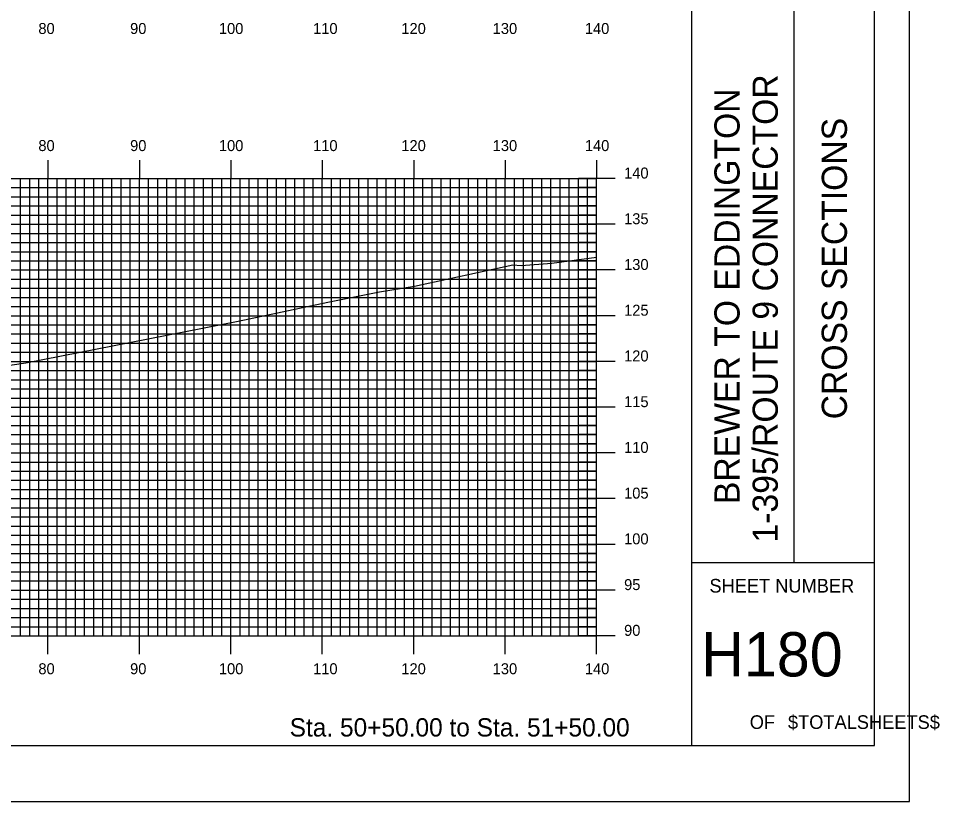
# Model space of a CAD drawing. Extents: x 1755495 to 1755838, y 442591 to 442811.
# Drawn here: x 1755737.3 to 1755838, y 442590.5 to 442676.2 of the extents above; entities that cross this region are included whole.
import ezdxf

# ---------------------------------------------------------------- set-up
doc = ezdxf.new("R2010")
doc.units = 0
for name, color, linetype in [('BORDER', 7, 'Continuous'), ('H_V ANNOTATION', 7, 'Continuous'), ('MAJOR', 7, 'Continuous'), ('MINOR', 7, 'Continuous'), ('PLOT BOUNDARY', 7, 'Continuous'), ('S_Roadway_Centerline', 7, 'Continuous')]:
    doc.layers.add(name, color=color, linetype=linetype)

msp = doc.modelspace()

# ---------------------------------------------------------------- linework, layer by layer
at = {"layer": 'BORDER'}
for p, q in [((1755810.94, 442596.67), (1755810.94, 442806.67)), ((1755822.13, 442616.67), (1755822.13, 442686.67)), ((1755810.94, 442616.67), (1755830.94, 442616.67))]:
    msp.add_line(p, q, dxfattribs=at)
msp.add_lwpolyline([(1755510.94, 442596.67), (1755830.94, 442596.67), (1755830.94, 442806.67), (1755510.94, 442806.67)], close=True, dxfattribs=at)
at = {"layer": 'MAJOR'}
for p, q in [((1755740.54, 442660.67), (1755740.54, 442658.67)), ((1755750.54, 442660.67), (1755750.54, 442658.67)), ((1755760.54, 442660.67), (1755760.54, 442658.67)), ((1755770.54, 442660.67), (1755770.54, 442658.67)), ((1755780.54, 442660.67), (1755780.54, 442658.67)), ((1755790.54, 442660.67), (1755790.54, 442658.67)), ((1755800.54, 442660.67), (1755800.54, 442658.67)), ((1755520.54, 442658.67), (1755800.54, 442658.67)), ((1755520.54, 442658.67), (1755800.54, 442658.67)), ((1755740.54, 442608.67), (1755740.54, 442658.67)), ((1755750.54, 442608.67), (1755750.54, 442658.67)), ((1755760.54, 442608.67), (1755760.54, 442658.67)), ((1755770.54, 442608.67), (1755770.54, 442658.67)), ((1755780.54, 442608.67), (1755780.54, 442658.67)), ((1755790.54, 442608.67), (1755790.54, 442658.67)), ((1755802.55, 442658.67), (1755798.54, 442658.67)), ((1755800.54, 442608.67), (1755800.54, 442658.67)), ((1755800.54, 442608.67), (1755800.54, 442658.67)), ((1755520.54, 442653.67), (1755800.54, 442653.67)), ((1755802.55, 442653.67), (1755798.54, 442653.67)), ((1755520.54, 442648.67), (1755800.54, 442648.67)), ((1755802.55, 442648.67), (1755798.54, 442648.67)), ((1755520.54, 442643.67), (1755800.54, 442643.67)), ((1755802.55, 442643.67), (1755798.54, 442643.67)), ((1755520.54, 442638.67), (1755800.54, 442638.67)), ((1755802.55, 442638.67), (1755798.54, 442638.67)), ((1755520.54, 442633.67), (1755800.54, 442633.67)), ((1755802.55, 442633.67), (1755798.54, 442633.67)), ((1755520.54, 442628.67), (1755800.54, 442628.67)), ((1755802.55, 442628.67), (1755798.54, 442628.67)), ((1755520.54, 442623.67), (1755800.54, 442623.67)), ((1755802.55, 442623.67), (1755798.54, 442623.67)), ((1755520.54, 442618.67), (1755800.54, 442618.67)), ((1755802.55, 442618.67), (1755798.54, 442618.67)), ((1755520.54, 442613.67), (1755800.54, 442613.67)), ((1755802.55, 442613.67), (1755798.54, 442613.67)), ((1755520.54, 442608.67), (1755800.54, 442608.67)), ((1755520.54, 442608.67), (1755800.54, 442608.67)), ((1755740.54, 442606.66), (1755740.54, 442608.67)), ((1755750.54, 442606.66), (1755750.54, 442608.67)), ((1755760.54, 442606.66), (1755760.54, 442608.67)), ((1755770.54, 442606.66), (1755770.54, 442608.67)), ((1755780.54, 442606.66), (1755780.54, 442608.67)), ((1755790.54, 442606.66), (1755790.54, 442608.67)), ((1755802.55, 442608.67), (1755798.54, 442608.67)), ((1755800.54, 442606.66), (1755800.54, 442608.67))]:
    msp.add_line(p, q, dxfattribs=at)
at = {"layer": 'MINOR'}
for p, q in [((1755737.54, 442608.67), (1755737.54, 442658.67)), ((1755738.54, 442608.67), (1755738.54, 442658.67)), ((1755739.54, 442608.67), (1755739.54, 442658.67)), ((1755741.54, 442608.67), (1755741.54, 442658.67)), ((1755742.54, 442608.67), (1755742.54, 442658.67)), ((1755743.54, 442608.67), (1755743.54, 442658.67)), ((1755744.54, 442608.67), (1755744.54, 442658.67)), ((1755745.54, 442608.67), (1755745.54, 442658.67)), ((1755746.54, 442608.67), (1755746.54, 442658.67)), ((1755747.54, 442608.67), (1755747.54, 442658.67)), ((1755748.54, 442608.67), (1755748.54, 442658.67)), ((1755749.54, 442608.67), (1755749.54, 442658.67)), ((1755751.54, 442608.67), (1755751.54, 442658.67)), ((1755752.54, 442608.67), (1755752.54, 442658.67)), ((1755753.54, 442608.67), (1755753.54, 442658.67)), ((1755754.54, 442608.67), (1755754.54, 442658.67)), ((1755755.54, 442608.67), (1755755.54, 442658.67)), ((1755756.54, 442608.67), (1755756.54, 442658.67)), ((1755757.54, 442608.67), (1755757.54, 442658.67)), ((1755758.54, 442608.67), (1755758.54, 442658.67)), ((1755759.54, 442608.67), (1755759.54, 442658.67)), ((1755761.54, 442608.67), (1755761.54, 442658.67)), ((1755762.54, 442608.67), (1755762.54, 442658.67)), ((1755763.54, 442608.67), (1755763.54, 442658.67)), ((1755764.54, 442608.67), (1755764.54, 442658.67)), ((1755765.54, 442608.67), (1755765.54, 442658.67)), ((1755766.54, 442608.67), (1755766.54, 442658.67)), ((1755767.54, 442608.67), (1755767.54, 442658.67)), ((1755768.54, 442608.67), (1755768.54, 442658.67)), ((1755769.54, 442608.67), (1755769.54, 442658.67)), ((1755771.54, 442608.67), (1755771.54, 442658.67)), ((1755772.54, 442608.67), (1755772.54, 442658.67)), ((1755773.54, 442608.67), (1755773.54, 442658.67)), ((1755774.54, 442608.67), (1755774.54, 442658.67)), ((1755775.54, 442608.67), (1755775.54, 442658.67)), ((1755776.54, 442608.67), (1755776.54, 442658.67)), ((1755777.54, 442608.67), (1755777.54, 442658.67)), ((1755778.54, 442608.67), (1755778.54, 442658.67)), ((1755779.54, 442608.67), (1755779.54, 442658.67)), ((1755781.54, 442608.67), (1755781.54, 442658.67)), ((1755782.54, 442608.67), (1755782.54, 442658.67)), ((1755783.54, 442608.67), (1755783.54, 442658.67)), ((1755784.54, 442608.67), (1755784.54, 442658.67)), ((1755785.54, 442608.67), (1755785.54, 442658.67)), ((1755786.54, 442608.67), (1755786.54, 442658.67)), ((1755787.54, 442608.67), (1755787.54, 442658.67)), ((1755788.54, 442608.67), (1755788.54, 442658.67)), ((1755789.54, 442608.67), (1755789.54, 442658.67)), ((1755791.54, 442608.67), (1755791.54, 442658.67)), ((1755792.54, 442608.67), (1755792.54, 442658.67)), ((1755793.54, 442608.67), (1755793.54, 442658.67)), ((1755794.54, 442608.67), (1755794.54, 442658.67)), ((1755795.54, 442608.67), (1755795.54, 442658.67)), ((1755796.54, 442608.67), (1755796.54, 442658.67)), ((1755797.54, 442608.67), (1755797.54, 442658.67)), ((1755798.54, 442608.67), (1755798.54, 442658.67)), ((1755799.54, 442608.67), (1755799.54, 442658.67)), ((1755520.54, 442657.67), (1755800.54, 442657.67)), ((1755520.54, 442656.67), (1755800.54, 442656.67)), ((1755800.54, 442657.67), (1755798.54, 442657.67)), ((1755800.54, 442656.67), (1755798.54, 442656.67)), ((1755520.54, 442655.67), (1755800.54, 442655.67)), ((1755800.54, 442655.67), (1755798.54, 442655.67)), ((1755520.54, 442654.67), (1755800.54, 442654.67)), ((1755800.54, 442654.67), (1755798.54, 442654.67)), ((1755520.54, 442652.67), (1755800.54, 442652.67)), ((1755800.54, 442652.67), (1755798.54, 442652.67)), ((1755520.54, 442651.67), (1755800.54, 442651.67)), ((1755800.54, 442651.67), (1755798.54, 442651.67)), ((1755520.54, 442650.67), (1755800.54, 442650.67)), ((1755800.54, 442650.67), (1755798.54, 442650.67)), ((1755520.54, 442649.67), (1755800.54, 442649.67)), ((1755800.54, 442649.67), (1755798.54, 442649.67)), ((1755520.54, 442647.67), (1755800.54, 442647.67)), ((1755800.54, 442647.67), (1755798.54, 442647.67)), ((1755520.54, 442646.67), (1755800.54, 442646.67)), ((1755800.54, 442646.67), (1755798.54, 442646.67)), ((1755520.54, 442645.67), (1755800.54, 442645.67)), ((1755800.54, 442645.67), (1755798.54, 442645.67)), ((1755520.54, 442644.67), (1755800.54, 442644.67)), ((1755800.54, 442644.67), (1755798.54, 442644.67)), ((1755520.54, 442642.67), (1755800.54, 442642.67)), ((1755800.54, 442642.67), (1755798.54, 442642.67)), ((1755520.54, 442641.67), (1755800.54, 442641.67)), ((1755800.54, 442641.67), (1755798.54, 442641.67)), ((1755520.54, 442640.67), (1755800.54, 442640.67)), ((1755800.54, 442640.67), (1755798.54, 442640.67)), ((1755520.54, 442639.67), (1755800.54, 442639.67)), ((1755800.54, 442639.67), (1755798.54, 442639.67)), ((1755520.54, 442637.67), (1755800.54, 442637.67)), ((1755800.54, 442637.67), (1755798.54, 442637.67)), ((1755520.54, 442636.67), (1755800.54, 442636.67)), ((1755800.54, 442636.67), (1755798.54, 442636.67)), ((1755520.54, 442635.67), (1755800.54, 442635.67)), ((1755800.54, 442635.67), (1755798.54, 442635.67)), ((1755520.54, 442634.67), (1755800.54, 442634.67)), ((1755800.54, 442634.67), (1755798.54, 442634.67)), ((1755520.54, 442632.67), (1755800.54, 442632.67)), ((1755800.54, 442632.67), (1755798.54, 442632.67)), ((1755520.54, 442631.67), (1755800.54, 442631.67)), ((1755800.54, 442631.67), (1755798.54, 442631.67)), ((1755520.54, 442630.67), (1755800.54, 442630.67)), ((1755800.54, 442630.67), (1755798.54, 442630.67)), ((1755520.54, 442629.67), (1755800.54, 442629.67)), ((1755800.54, 442629.67), (1755798.54, 442629.67)), ((1755520.54, 442627.67), (1755800.54, 442627.67)), ((1755800.54, 442627.67), (1755798.54, 442627.67)), ((1755520.54, 442626.67), (1755800.54, 442626.67)), ((1755800.54, 442626.67), (1755798.54, 442626.67)), ((1755520.54, 442625.67), (1755800.54, 442625.67)), ((1755800.54, 442625.67), (1755798.54, 442625.67)), ((1755520.54, 442624.67), (1755800.54, 442624.67)), ((1755800.54, 442624.67), (1755798.54, 442624.67)), ((1755520.54, 442622.67), (1755800.54, 442622.67)), ((1755800.54, 442622.67), (1755798.54, 442622.67)), ((1755520.54, 442621.67), (1755800.54, 442621.67)), ((1755800.54, 442621.67), (1755798.54, 442621.67)), ((1755520.54, 442620.67), (1755800.54, 442620.67)), ((1755800.54, 442620.67), (1755798.54, 442620.67)), ((1755520.54, 442619.67), (1755800.54, 442619.67)), ((1755800.54, 442619.67), (1755798.54, 442619.67)), ((1755520.54, 442617.67), (1755800.54, 442617.67)), ((1755800.54, 442617.67), (1755798.54, 442617.67)), ((1755520.54, 442616.67), (1755800.54, 442616.67)), ((1755800.54, 442616.67), (1755798.54, 442616.67)), ((1755520.54, 442615.67), (1755800.54, 442615.67)), ((1755800.54, 442615.67), (1755798.54, 442615.67)), ((1755520.54, 442614.67), (1755800.54, 442614.67)), ((1755800.54, 442614.67), (1755798.54, 442614.67)), ((1755520.54, 442612.67), (1755800.54, 442612.67)), ((1755800.54, 442612.67), (1755798.54, 442612.67)), ((1755520.54, 442611.67), (1755800.54, 442611.67)), ((1755800.54, 442611.67), (1755798.54, 442611.67)), ((1755520.54, 442610.67), (1755800.54, 442610.67)), ((1755800.54, 442610.67), (1755798.54, 442610.67)), ((1755520.54, 442609.67), (1755800.54, 442609.67)), ((1755800.54, 442609.67), (1755798.54, 442609.67))]:
    msp.add_line(p, q, dxfattribs=at)
at = {"layer": 'PLOT BOUNDARY'}
msp.add_lwpolyline([(1755494.76, 442590.55), (1755834.76, 442590.55), (1755834.76, 442810.55), (1755494.76, 442810.55)], close=True, dxfattribs=at)
at = {"layer": 'S_Roadway_Centerline'}
msp.add_lwpolyline([(1755603.68, 442624.99), (1755613.92, 442626.39), (1755622.91, 442627.84), (1755630.67, 442628.12), (1755642.51, 442628.33), (1755650.1, 442628.26), (1755662.02, 442627.85), (1755663.48, 442627.82), (1755665.43, 442627.89), (1755686.03, 442630.02), (1755694.09, 442630.78), (1755697.38, 442631.29), (1755699.52, 442631.3), (1755725.38, 442636.54), (1755733.09, 442637.8), (1755738.12, 442638.52), (1755761.32, 442643.07), (1755771.13, 442645.16), (1755776.81, 442646.28), (1755780.62, 442646.9), (1755791.38, 442649.24), (1755792.27, 442649.15), (1755795.64, 442649.41), (1755800.54, 442650.07)], dxfattribs=at)

# ---------------------------------------------------------------- texts
at = {"layer": 'BORDER'}
for s, p in [('1-395/ROUTE 9 CONNECTOR', (1755820.35, 442618.87)), ('BREWER TO EDDINGTON', (1755816.17, 442623.07)), ('CROSS SECTIONS', (1755827.91, 442632.34))]:
    msp.add_text(s, height=2.7557, rotation=90, dxfattribs=at).set_placement(p)
for s, height, p in [('SHEET NUMBER', 1.4905, (1755812.87, 442613.4)), ('H180', 4.839, (1755811.97, 442604.23)), ('OF', 1.491, (1755817.28, 442598.49)), ('$TOTALSHEETS$', 1.4905, (1755821.46, 442598.49))]:
    msp.add_text(s, height=height, dxfattribs=at).set_placement(p)
at = {"layer": 'H_V ANNOTATION'}
for s, height, p in [('80', 1.2, (1755739.49, 442674.47)), ('90', 1.2, (1755749.52, 442674.47)), ('100', 1.2, (1755759.23, 442674.47)), ('110', 1.2, (1755769.53, 442674.47)), ('120', 1.2, (1755779.18, 442674.47)), ('130', 1.2, (1755789.17, 442674.47)), ('140', 1.2, (1755799.25, 442674.47)), ('80', 1.2, (1755739.49, 442661.67)), ('90', 1.2, (1755749.52, 442661.67)), ('100', 1.2, (1755759.23, 442661.67)), ('110', 1.2, (1755769.53, 442661.67)), ('120', 1.2, (1755779.18, 442661.67)), ('130', 1.2, (1755789.17, 442661.67)), ('140', 1.2, (1755799.25, 442661.67)), ('140', 1.2, (1755803.54, 442658.67)), ('135', 1.2, (1755803.54, 442653.67)), ('130', 1.2, (1755803.54, 442648.67)), ('125', 1.2, (1755803.54, 442643.67)), ('120', 1.2, (1755803.54, 442638.67)), ('115', 1.2, (1755803.54, 442633.67)), ('110', 1.2, (1755803.54, 442628.67)), ('105', 1.2, (1755803.54, 442623.67)), ('100', 1.2, (1755803.54, 442618.67)), ('95', 1.2, (1755803.54, 442613.67)), ('90', 1.2, (1755803.54, 442608.67)), ('80', 1.2, (1755739.49, 442604.47)), ('90', 1.2, (1755749.52, 442604.47)), ('100', 1.2, (1755759.23, 442604.47)), ('110', 1.2, (1755769.53, 442604.47)), ('120', 1.2, (1755779.18, 442604.47)), ('130', 1.2, (1755789.17, 442604.47)), ('140', 1.2, (1755799.25, 442604.47)), ('Sta. 50+50.00 to Sta. 51+50.00', 2.0004, (1755766.97, 442597.66))]:
    msp.add_text(s, height=height, dxfattribs=at).set_placement(p)

doc.saveas('drawing.dxf')
